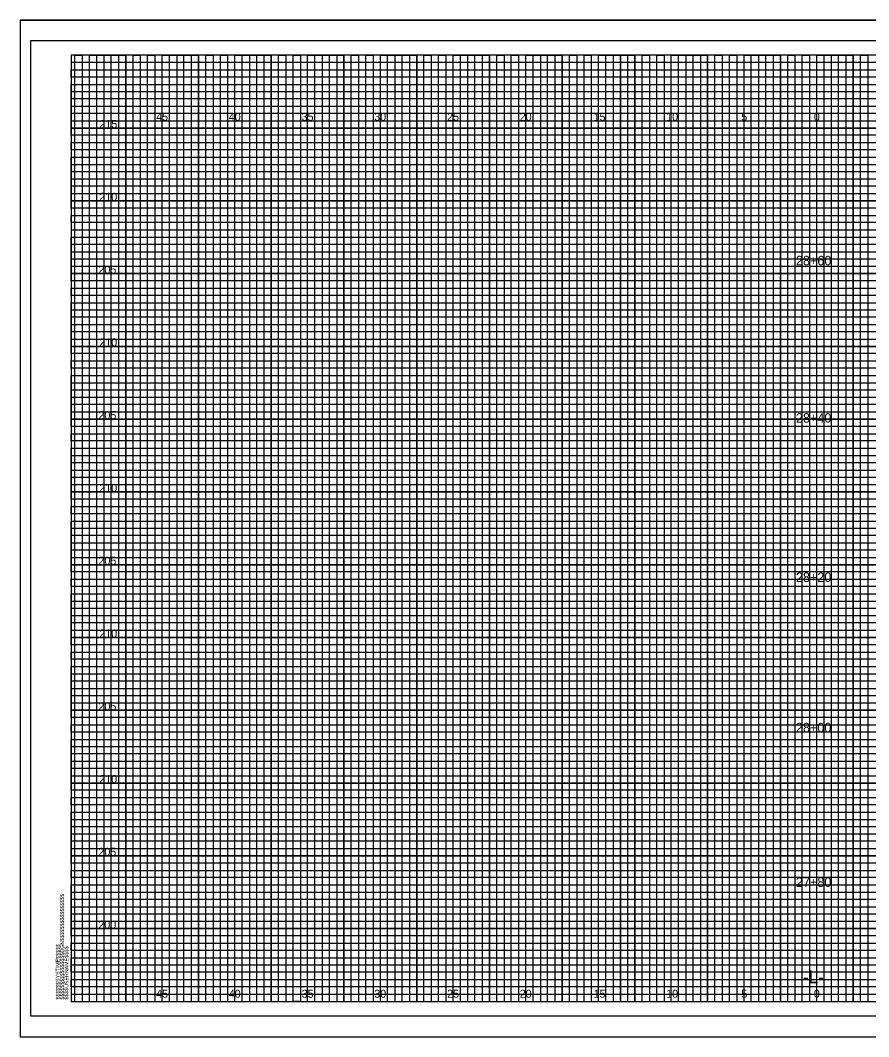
# Model space of a CAD drawing. Extents: x -4 to 103, y -2 to 6583.
# Drawn here: x -3.5 to 54.8, y 1768.2 to 1838 of the extents above; entities that cross this region are included whole.
import ezdxf

# ---------------------------------------------------------------- set-up
doc = ezdxf.new("R2010")
doc.units = 0
for name, color, linetype in [('Prop XS Alignment Label', 7, 'Continuous'), ('Prop XS Elevation Labels', 7, 'Continuous'), ('Prop XS Offset Labels', 7, 'Continuous'), ('Prop XS Station Labels', 7, 'Continuous'), ('Sheet Cross Section CELL', 7, 'Continuous'), ('Sheet Cross Section Grid Major CELL', 7, 'Continuous'), ('Sheet Cross Section Grid Middle CELL', 7, 'Continuous'), ('Sheet Cutting Line CELL', 7, 'Continuous'), ('Sheet DOT Grid CELL', 7, 'Continuous'), ('Sheet Plot Border Inside CELL', 7, 'Continuous'), ('Sheet Plot Border Outside CELL', 7, 'Continuous')]:
    doc.layers.add(name, color=color, linetype=linetype)

msp = doc.modelspace()

# ---------------------------------------------------------------- linework, layer by layer
at = {"layer": 'Sheet Cross Section CELL'}
msp.add_lwpolyline([(102.5, 1835.625), (0, 1835.625), (0, 1770.625), (102.5, 1770.625)], close=True, dxfattribs=at)
at = {"layer": 'Sheet Cross Section Grid Major CELL'}
for points in [[(1.25, 1770.625), (1.25, 1835.625), (3.75, 1835.625), (3.75, 1770.625), (6.25, 1770.625), (6.25, 1835.625), (8.75, 1835.625), (8.75, 1770.625), (11.25, 1770.625), (11.25, 1835.625), (13.75, 1835.625), (13.75, 1770.625), (16.25, 1770.625), (16.25, 1835.625), (18.75, 1835.625), (18.75, 1770.625), (21.25, 1770.625), (21.25, 1835.625), (23.75, 1835.625), (23.75, 1770.625), (26.25, 1770.625), (26.25, 1835.625), (28.75, 1835.625), (28.75, 1770.625), (31.25, 1770.625), (31.25, 1835.625), (33.75, 1835.625), (33.75, 1770.625), (36.25, 1770.625), (36.25, 1835.625), (38.75, 1835.625), (38.75, 1770.625), (41.25, 1770.625), (41.25, 1835.625), (43.75, 1835.625), (43.75, 1770.625), (46.25, 1770.625), (46.25, 1835.625), (48.75, 1835.625), (48.75, 1770.625), (51.25, 1770.625), (51.25, 1835.625), (53.75, 1835.625), (53.75, 1770.625)], [(102.5, 1830.625), (0, 1830.625), (0, 1833.125), (74.25, 1833.125)], [(102.5, 1825.625), (0, 1825.625), (0, 1828.125), (102.5, 1828.125)], [(102.5, 1820.625), (0, 1820.625), (0, 1823.125), (102.5, 1823.125)], [(102.5, 1815.625), (0, 1815.625), (0, 1818.125), (102.5, 1818.125)], [(102.5, 1810.625), (0, 1810.625), (0, 1813.125), (102.5, 1813.125)], [(102.5, 1805.625), (0, 1805.625), (0, 1808.125), (102.5, 1808.125)], [(102.5, 1800.625), (0, 1800.625), (0, 1803.125), (102.5, 1803.125)], [(102.5, 1795.625), (0, 1795.625), (0, 1798.125), (102.5, 1798.125)], [(102.5, 1790.625), (0, 1790.625), (0, 1793.125), (102.5, 1793.125)], [(102.5, 1785.625), (0, 1785.625), (0, 1788.125), (102.5, 1788.125)], [(102.5, 1780.625), (0, 1780.625), (0, 1783.125), (102.5, 1783.125)], [(102.5, 1775.625), (0, 1775.625), (0, 1778.125), (102.5, 1778.125)], [(0, 1773.125), (102.5, 1773.125)]]:
    msp.add_lwpolyline(points, dxfattribs=at)
at = {"layer": 'Sheet Cross Section Grid Middle CELL'}
for points in [[(0, 1832.625), (0, 1833.625), (74.25, 1833.625), (74.25, 1834.125), (0, 1834.125), (0, 1834.625), (74.25, 1834.625), (74.25, 1835.125), (0, 1835.125)], [(0.25, 1770.625), (0.25, 1835.625), (0.75, 1835.625), (0.75, 1770.625), (1.75, 1770.625), (1.75, 1835.625), (2.25, 1835.625), (2.25, 1770.625), (2.75, 1770.625), (2.75, 1835.625), (3.25, 1835.625), (3.25, 1770.625), (4.25, 1770.625), (4.25, 1835.625), (4.75, 1835.625), (4.75, 1770.625), (5.25, 1770.625), (5.25, 1835.625), (5.75, 1835.625), (5.75, 1770.625), (6.75, 1770.625), (6.75, 1835.625), (7.25, 1835.625), (7.25, 1770.625), (7.75, 1770.625), (7.75, 1835.625), (8.25, 1835.625), (8.25, 1770.625), (9.25, 1770.625), (9.25, 1835.625), (9.75, 1835.625), (9.75, 1770.625), (10.25, 1770.625), (10.25, 1835.625), (10.75, 1835.625), (10.75, 1770.625), (11.75, 1770.625), (11.75, 1835.625), (12.25, 1835.625), (12.25, 1770.625), (12.75, 1770.625), (12.75, 1835.625), (13.25, 1835.625), (13.25, 1770.625), (14.25, 1770.625), (14.25, 1835.625), (14.75, 1835.625), (14.75, 1770.625), (15.75, 1770.625), (15.25, 1770.625), (15.25, 1835.625), (15.75, 1835.625), (15.75, 1770.625), (16.75, 1770.625), (16.75, 1835.625), (17.25, 1835.625), (17.25, 1770.625), (17.75, 1770.625), (17.75, 1835.625), (18.25, 1835.625), (18.25, 1770.625), (19.25, 1770.625), (19.25, 1835.625), (19.75, 1835.625), (19.75, 1770.625), (20.25, 1770.625), (20.25, 1835.625), (20.75, 1835.625), (20.75, 1770.625), (21.75, 1770.625), (21.75, 1835.625), (22.25, 1835.625), (22.25, 1770.625), (22.75, 1770.625), (22.75, 1835.625), (23.25, 1835.625), (23.25, 1770.625), (24.25, 1770.625), (24.25, 1835.625), (24.75, 1835.625), (24.75, 1770.625), (25.25, 1770.625), (25.25, 1835.625), (25.75, 1835.625), (25.75, 1770.625), (26.75, 1770.625), (26.75, 1835.625), (27.25, 1835.625), (27.25, 1770.625), (27.75, 1770.625), (27.75, 1835.625), (28.25, 1835.625), (28.25, 1770.625), (29.25, 1770.625), (29.25, 1835.625), (29.75, 1835.625), (29.75, 1770.625), (30.25, 1770.625), (30.25, 1835.625), (30.75, 1835.625), (30.75, 1770.625)], [(30.75, 1770.625), (31.75, 1770.625), (31.75, 1835.625), (32.25, 1835.625), (32.25, 1770.625), (32.75, 1770.625), (32.75, 1835.625), (33.25, 1835.625), (33.25, 1770.625), (34.25, 1770.625), (34.25, 1835.625), (34.75, 1835.625), (34.75, 1770.625), (35.25, 1770.625), (35.25, 1835.625), (35.75, 1835.625), (35.75, 1770.625), (36.75, 1770.625), (36.75, 1835.625), (37.25, 1835.625), (37.25, 1770.625), (37.75, 1770.625), (37.75, 1835.625), (37.75, 1770.625)], [(38.25, 1835.625), (38.25, 1770.625), (39.25, 1770.625), (39.25, 1835.625), (39.75, 1835.625), (39.75, 1770.625), (40.25, 1770.625), (40.25, 1835.625), (40.75, 1835.625), (40.75, 1770.625), (41.75, 1770.625), (41.75, 1835.625), (42.25, 1835.625), (42.25, 1770.625), (42.75, 1770.625), (42.75, 1835.625), (43.25, 1835.625), (43.25, 1770.625), (43.75, 1770.625), (44.25, 1770.625), (44.25, 1835.625), (44.75, 1835.625), (44.75, 1770.625), (45.25, 1770.625), (45.25, 1835.625), (45.75, 1835.625), (45.75, 1770.625), (46.75, 1770.625), (46.75, 1835.625), (47.25, 1835.625), (47.25, 1770.625), (47.75, 1770.625), (47.75, 1835.625), (48.25, 1835.625), (48.25, 1770.625), (49.25, 1770.625), (49.25, 1835.625), (49.75, 1835.625), (49.75, 1770.625), (50.25, 1770.625), (50.25, 1835.625), (50.75, 1835.625), (50.75, 1770.625), (51.75, 1770.625), (51.75, 1835.625), (52.25, 1835.625), (52.25, 1770.625), (52.75, 1770.625), (52.75, 1835.625), (53.25, 1835.625), (53.25, 1770.625), (54.25, 1770.625), (54.25, 1835.625), (54.75, 1835.625), (54.75, 1770.625), (55.25, 1770.625)], [(102.5, 1832.625), (0, 1832.625)], [(102.5, 1831.625), (0, 1831.625), (0, 1832.125), (102.5, 1832.125)], [(102.5, 1830.125), (0, 1830.125), (0, 1831.125), (102.5, 1831.125)], [(102.5, 1829.125), (0, 1829.125), (0, 1829.625), (102.5, 1829.625)], [(102.5, 1827.625), (0, 1827.625), (0, 1828.625), (102.5, 1828.625)], [(102.5, 1826.625), (0, 1826.625), (0, 1827.125), (102.5, 1827.125)], [(102.5, 1825.125), (0, 1825.125), (0, 1826.125), (102.5, 1826.125)], [(102.5, 1824.125), (0, 1824.125), (0, 1824.625), (102.5, 1824.625)], [(0, 1823.625), (102.5, 1823.625)], [(102.5, 1822.625), (0, 1822.625)], [(102.5, 1821.625), (0, 1821.625), (0, 1822.125), (102.5, 1822.125)], [(102.5, 1820.125), (0, 1820.125), (0, 1821.125), (102.5, 1821.125)], [(102.5, 1819.125), (0, 1819.125), (0, 1819.625), (102.5, 1819.625)], [(102.5, 1817.625), (0, 1817.625), (0, 1818.625), (102.5, 1818.625)], [(102.5, 1816.625), (0, 1816.625), (0, 1817.125), (102.5, 1817.125)], [(102.5, 1815.125), (0, 1815.125), (0, 1816.125), (102.5, 1816.125)], [(102.5, 1814.125), (0, 1814.125), (0, 1814.625), (102.5, 1814.625)], [(102.5, 1812.625), (0, 1812.625), (0, 1813.625), (102.5, 1813.625)], [(102.5, 1811.625), (0, 1811.625), (0, 1812.125), (102.5, 1812.125)], [(102.5, 1810.125), (0, 1810.125), (0, 1811.125), (102.5, 1811.125)], [(102.5, 1809.125), (0, 1809.125), (0, 1809.625), (102.5, 1809.625)], [(102.5, 1807.625), (0, 1807.625), (0, 1808.625), (102.5, 1808.625)], [(102.5, 1806.625), (0, 1806.625), (0, 1807.125), (102.5, 1807.125)], [(102.5, 1805.125), (0, 1805.125), (0, 1806.125), (102.5, 1806.125)], [(102.5, 1804.125), (0, 1804.125), (0, 1804.625), (102.5, 1804.625)], [(102.5, 1802.625), (0, 1802.625), (0, 1803.625), (102.5, 1803.625)], [(102.5, 1801.625), (0, 1801.625), (0, 1802.125)], [(0, 1802.125), (102.5, 1802.125)], [(102.5, 1800.125), (0, 1800.125), (0, 1801.125), (102.5, 1801.125)], [(102.5, 1799.125), (0, 1799.125), (0, 1799.625), (102.5, 1799.625)], [(102.5, 1797.625), (0, 1797.625), (0, 1798.625), (102.5, 1798.625)], [(102.5, 1796.625), (0, 1796.625), (0, 1797.125), (102.5, 1797.125)], [(102.5, 1795.125), (0, 1795.125), (0, 1796.125), (102.5, 1796.125)], [(102.5, 1794.125), (0, 1794.125), (0, 1794.625), (102.5, 1794.625)], [(102.5, 1792.625), (0, 1792.625), (0, 1793.625), (102.5, 1793.625)], [(102.5, 1791.625), (0, 1791.625), (0, 1792.125), (102.5, 1792.125)], [(102.5, 1790.125), (0, 1790.125), (0, 1791.125), (102.5, 1791.125)], [(102.5, 1789.125), (0, 1789.125), (0, 1789.625), (102.5, 1789.625)], [(102.5, 1787.625), (0, 1787.625), (0, 1788.625), (102.5, 1788.625)], [(102.5, 1786.625), (0, 1786.625), (0, 1787.125), (102.5, 1787.125)], [(102.5, 1785.125), (0, 1785.125), (0, 1786.125), (102.5, 1786.125)], [(102.5, 1784.125), (0, 1784.125), (0, 1784.625), (102.5, 1784.625)], [(102.5, 1782.625), (0, 1782.625), (0, 1783.625), (102.5, 1783.625)], [(102.5, 1781.625), (0, 1781.625), (0, 1782.125), (102.5, 1782.125)], [(102.5, 1780.125), (0, 1780.125), (0, 1781.125), (102.5, 1781.125)], [(102.5, 1779.125), (0, 1779.125), (0, 1779.625), (102.5, 1779.625)], [(102.5, 1777.625), (0, 1777.625), (0, 1778.625), (102.5, 1778.625)], [(102.5, 1776.625), (0, 1776.625), (0, 1777.125), (102.5, 1777.125)], [(102.5, 1775.125), (0, 1775.125), (0, 1776.125), (102.5, 1776.125)], [(102.5, 1774.125), (0, 1774.125), (0, 1774.625), (102.5, 1774.625)], [(102.5, 1772.625), (0, 1772.625), (0, 1773.625), (102.5, 1773.625)], [(102.5, 1771.625), (0, 1771.625), (0, 1772.125), (102.5, 1772.125)], [(0, 1771.125), (102.5, 1771.125)]]:
    msp.add_lwpolyline(points, dxfattribs=at)
at = {"layer": 'Sheet Cutting Line CELL'}
for p, q in [((-3.5, 1838.025), (103.4, 1838.025)), ((-3.5, 1838.025), (-3.5, 1768.2)), ((-3.5, 1768.2), (103.4, 1768.2))]:
    msp.add_line(p, q, dxfattribs=at)
at = {"layer": 'Sheet DOT Grid CELL'}
for p, q in [((1.25, 1770.625), (1.25, 1835.625)), ((3.75, 1770.625), (3.75, 1835.625)), ((6.25, 1770.625), (6.25, 1835.625)), ((8.75, 1770.625), (8.75, 1835.625)), ((11.25, 1770.625), (11.25, 1835.625)), ((13.75, 1770.625), (13.75, 1835.625)), ((16.25, 1770.625), (16.25, 1835.625)), ((18.75, 1770.625), (18.75, 1835.625)), ((21.25, 1770.625), (21.25, 1835.625)), ((23.75, 1770.625), (23.75, 1835.625)), ((26.25, 1770.625), (26.25, 1835.625)), ((28.75, 1770.625), (28.75, 1835.625)), ((31.25, 1770.625), (31.25, 1835.625)), ((33.75, 1770.625), (33.75, 1835.625)), ((36.25, 1770.625), (36.25, 1835.625)), ((38.75, 1770.625), (38.75, 1835.625)), ((41.25, 1770.625), (41.25, 1835.625)), ((43.75, 1770.625), (43.75, 1835.625)), ((46.25, 1770.625), (46.25, 1835.625)), ((48.75, 1770.625), (48.75, 1835.625)), ((51.25, 1770.625), (51.25, 1835.625)), ((53.75, 1770.625), (53.75, 1835.625)), ((0, 1833.125), (74.25, 1833.125)), ((0, 1830.625), (102.5, 1830.625)), ((0, 1828.125), (102.5, 1828.125)), ((0, 1825.625), (102.5, 1825.625)), ((0, 1823.125), (102.5, 1823.125)), ((0, 1820.625), (102.5, 1820.625)), ((0, 1818.125), (102.5, 1818.125)), ((0, 1815.625), (102.5, 1815.625)), ((0, 1813.125), (102.5, 1813.125)), ((0, 1810.625), (102.5, 1810.625)), ((0, 1808.125), (102.5, 1808.125)), ((0, 1805.625), (102.5, 1805.625)), ((0, 1803.125), (102.5, 1803.125)), ((0, 1800.625), (102.5, 1800.625)), ((0, 1798.125), (102.5, 1798.125)), ((0, 1795.625), (102.5, 1795.625)), ((0, 1793.125), (102.5, 1793.125)), ((0, 1790.625), (102.5, 1790.625)), ((0, 1788.125), (102.5, 1788.125)), ((0, 1785.625), (102.5, 1785.625)), ((0, 1783.125), (102.5, 1783.125)), ((0, 1780.625), (102.5, 1780.625)), ((0, 1778.125), (102.5, 1778.125)), ((0, 1775.625), (102.5, 1775.625)), ((0, 1773.125), (102.5, 1773.125))]:
    msp.add_line(p, q, dxfattribs=at)
at = {"layer": 'Sheet Plot Border Inside CELL'}
msp.add_lwpolyline([(103, 1836.625), (-2.8, 1836.625), (-2.8, 1769.625), (103, 1769.625)], close=True, dxfattribs=at)
at = {"layer": 'Sheet Plot Border Outside CELL'}
msp.add_lwpolyline([(103.4, 1838.025), (-3.5, 1838.025), (-3.5, 1768.2), (103.4, 1768.2)], close=True, dxfattribs=at)

# ---------------------------------------------------------------- texts
at = {"layer": 'Prop XS Alignment Label'}
msp.add_text('-L-', height=0.875, dxfattribs=at).set_placement((50.307, 1771.875))
at = {"layer": 'Prop XS Elevation Labels'}
for s, p in [('215', (1.938, 1830.625)), ('210', (1.93, 1825.625)), ('205', (1.872, 1820.625)), ('210', (1.93, 1815.625)), ('205', (1.872, 1810.625)), ('210', (1.93, 1805.625)), ('205', (1.872, 1800.625)), ('210', (1.93, 1795.625)), ('205', (1.872, 1790.625)), ('210', (1.93, 1785.625)), ('205', (1.872, 1780.625)), ('200', (1.864, 1775.625))]:
    msp.add_text(s, height=0.55, dxfattribs=at).set_placement(p)
at = {"layer": 'Prop XS Offset Labels'}
for s, p in [('45', (5.84, 1831.125)), ('40', (10.831, 1831.125)), ('35', (15.84, 1831.125)), ('30', (20.831, 1831.125)), ('25', (25.84, 1831.125)), ('20', (30.831, 1831.125)), ('15', (35.906, 1831.125)), ('10', (40.897, 1831.125)), ('5', (46.057, 1831.125)), ('0', (51.049, 1831.125)), ('0', (51.049, 1831.125)), ('45', (5.84, 1770.875)), ('40', (10.831, 1770.875)), ('35', (15.84, 1770.875)), ('30', (20.831, 1770.875)), ('25', (25.84, 1770.875)), ('20', (30.831, 1770.875)), ('15', (35.906, 1770.875)), ('10', (40.897, 1770.875)), ('5', (46.057, 1770.875)), ('0', (51.049, 1770.875)), ('0', (51.049, 1770.875))]:
    msp.add_text(s, height=0.55, dxfattribs=at).set_placement(p)
at = {"layer": 'Prop XS Station Labels'}
for s, p in [('28+60', (49.816, 1821.196)), ('28+40', (49.816, 1810.384)), ('28+20', (49.816, 1799.44)), ('28+00', (49.816, 1789.111)), ('27+80', (49.816, 1778.493))]:
    msp.add_text(s, height=0.65, dxfattribs=at).set_placement(p)
at = {"layer": 'Sheet Cross Section CELL'}
for s, p in [('$$$$$$$$$$$$$$$$DGN$$$$$$$$$$$$$$$$', (-0.5, 1770.75)), ('$$$$$$SYSTIME$$$$$', (-0.797, 1770.75)), ('$$$$USERNAME$$$$', (-0.2, 1770.75))]:
    msp.add_text(s, height=0.2625, rotation=90, dxfattribs=at).set_placement(p)
at = {"layer": 'Sheet Cross Section Grid Major CELL'}
msp.add_text('040397', height=0.0025, rotation=90, dxfattribs=at).set_placement((-0.001, 1835.611))

doc.saveas('drawing.dxf')
